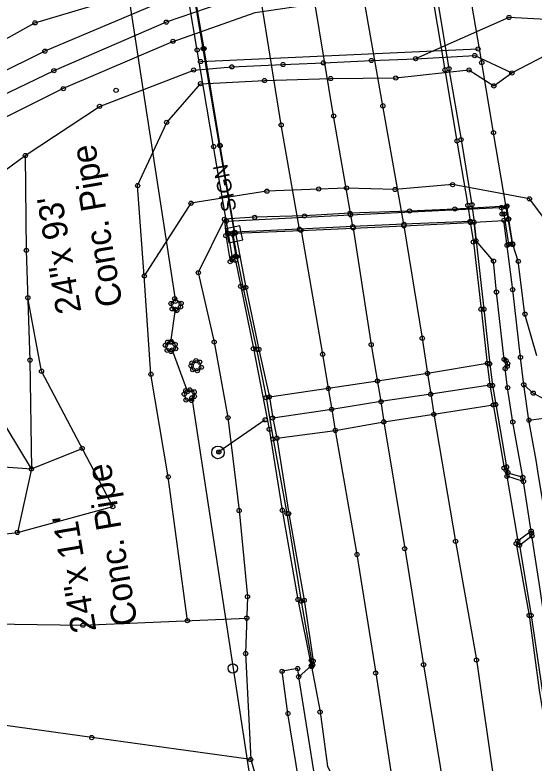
# Model space of a CAD drawing. Extents: x 21481721 to 21494985, y 8063982 to 8084842.
# Drawn here: x 21488039.9 to 21488164.1, y 8075079.6 to 8075258.6 of the extents above; entities that cross this region are included whole.
import ezdxf

# ---------------------------------------------------------------- set-up
doc = ezdxf.new("R2010")
doc.units = 0
for name, color, linetype in [('Bridge', 7, 'Continuous'), ('Default', 7, 'Continuous'), ('Drainage', 7, 'Continuous'), ('EXT_BL', 7, 'Continuous'), ('EXT_C', 7, 'Continuous'), ('EXT_CON', 7, 'Continuous'), ('EXT_CU', 7, 'Continuous'), ('EXT_D', 7, 'Continuous'), ('EXT_ENP', 7, 'Continuous'), ('EXT_EP', 7, 'Continuous'), ('EXT_GU', 7, 'Continuous'), ('EXT_SWK', 7, 'Continuous'), ('Roadways', 7, 'Continuous'), ('SurControl', 7, 'Continuous'), ('SurDrainage', 7, 'Continuous'), ('SurPointsNonDTM', 7, 'Continuous'), ('SurRoadPoints', 7, 'Continuous'), ('SurSurveyPoints', 7, 'Continuous'), ('Text', 7, 'Continuous')]:
    doc.layers.add(name, color=color, linetype=linetype)

msp = doc.modelspace()

# ---------------------------------------------------------------- linework, layer by layer
at = {"layer": 'Bridge'}
for points in [[(21488133.02, 8075208.53), (21488127.97, 8075236.87), (21488123.23, 8075263.68), (21488118.73, 8075292.88), (21488114.06, 8075318.67), (21488109.96, 8075344.62), (21488105.47, 8075369.72), (21488103.21, 8075384.48)], [(21488120.08, 8075385.72), (21488123.73, 8075364.06), (21488126.6, 8075347.14), (21488129.6, 8075329.59), (21488132.36, 8075313.39), (21488135.39, 8075295.32), (21488138.2, 8075278.59), (21488141.09, 8075261.71), (21488143.79, 8075245.75), (21488146.67, 8075228.8), (21488149.29, 8075213.2), (21488149.78, 8075209.03)], [(21488091.01, 8075206.3), (21488087.47, 8075227.14), (21488083.52, 8075250.23), (21488079.53, 8075273.88), (21488075.57, 8075297.2), (21488071.55, 8075321.1), (21488067.69, 8075343.72), (21488063.6, 8075368.19), (21488061.09, 8075383)], [(21488091.84, 8075206.37), (21488092.44, 8075206.59), (21488088.9, 8075227.4), (21488084.96, 8075250.55), (21488081, 8075274.15), (21488077.07, 8075297.44), (21488073.03, 8075321.28), (21488069.2, 8075343.93), (21488065.05, 8075368.47), (21488062.58, 8075383.09)], [(21488108, 8075207.36), (21488103.64, 8075232.31), (21488099.01, 8075261.23), (21488094.1, 8075289.47), (21488089.69, 8075316), (21488085.29, 8075341.96), (21488081.5, 8075365.43), (21488078.51, 8075383.22)], [(21488157.46, 8075212.67), (21488154.44, 8075230.46), (21488151.63, 8075247.25), (21488148.78, 8075264.05), (21488145.96, 8075280.82), (21488143.17, 8075297.55), (21488140.18, 8075315.22), (21488137.31, 8075331.99), (21488134.49, 8075348.81), (21488131.67, 8075365.48), (21488128.59, 8075383.27)], [(21488122.72, 8075363.95), (21488125.61, 8075347.18), (21488128.66, 8075329.41), (21488131.37, 8075313.38), (21488134.42, 8075295.1), (21488137.22, 8075278.46), (21488140.11, 8075261.55), (21488142.83, 8075245.48), (21488145.7, 8075228.45), (21488148.31, 8075213.06), (21488148.87, 8075209.24), (21488133.02, 8075208.53), (21488120.76, 8075207.97), (21488108, 8075207.36), (21488092.57, 8075206.62), (21488089.02, 8075227.38), (21488085.17, 8075250.55), (21488081.17, 8075274.1), (21488077.22, 8075297.45), (21488073.22, 8075321.29), (21488069.33, 8075343.94), (21488065.2, 8075368.55)]]:
    msp.add_lwpolyline(points, dxfattribs=at)
at = {"layer": 'Default'}
for p, q in [((21488150.73, 8075250.49), (21488150.73, 8075250.49)), ((21488084.33, 8075247.48), (21488084.33, 8075247.48))]:
    msp.add_line(p, q, dxfattribs=at)
for points in [[(21488120.76, 8075207.97), (21488116.18, 8075234.46), (21488111.59, 8075262.1), (21488106.7, 8075291.13), (21488102.31, 8075316.99), (21488098.02, 8075342.81), (21488093.73, 8075367.7), (21488091.12, 8075383.76)], [(21488084.33, 8075247.48), (21488150.73, 8075250.49)]]:
    msp.add_lwpolyline(points, dxfattribs=at)
at = {"layer": 'Drainage'}
for points in [[(21488064.32, 8075281.58), (21488078.34, 8075190.09)], [(21488077.22, 8075180.31), (21488078.31, 8075188.18)], [(21488077.53, 8075178.43), (21488081.18, 8075168.46)], [(21488082.26, 8075166.99), (21488119.44, 8074923.49)], [(21488099.78, 8075161.72), (21488088.7, 8075154.04)]]:
    msp.add_lwpolyline(points, dxfattribs=at)
at = {"layer": 'EXT_BL'}
for points in [[(21488255.94, 8075198.96), (21488256.72, 8075203.02), (21488252.15, 8075209.24), (21488240.15, 8075219.03), (21488220.61, 8075234.38), (21488204.16, 8075245.22), (21488188.67, 8075252.27), (21488174.57, 8075256.89), (21488165.62, 8075257.6), (21488158.14, 8075258.04), (21488135.81, 8075248.16)], [(21488081.2, 8075113.66), (21488076.62, 8075148.09), (21488072.47, 8075172.65), (21488070.88, 8075196.18), (21488069.27, 8075217.8), (21488076.23, 8075232.93), (21488084.31, 8075242.19), (21488099.64, 8075242.93), (21488115.47, 8075243.41), (21488131.06, 8075243.56), (21488148.57, 8075245.47), (21488154.52, 8075241.65), (21488158.85, 8075244.75), (21488168.94, 8075250.03), (21488180.68, 8075251.09), (21488194.28, 8075245.62), (21488207.18, 8075239.37), (21488220.09, 8075230.45), (21488233.03, 8075221.09), (21488244.21, 8075211.44), (21488255.94, 8075198.96)], [(21487989.15, 8075194.82), (21488024.32, 8075211.79), (21488042.4, 8075224.99), (21488060.17, 8075236.75), (21488082.7, 8075245.46), (21488091.82, 8075246.21), (21488104.06, 8075246.76), (21488113.72, 8075247.16), (21488125.22, 8075247.74), (21488135.81, 8075248.16), (21488149.96, 8075248.91), (21488158.85, 8075244.75)], [(21488042.4, 8075224.99), (21488042.63, 8075202.29), (21488043.51, 8075176.03), (21488043.85, 8075149.99), (21488040.5, 8075134.78)], [(21488174.3, 8075199.67), (21488163.05, 8075214.63), (21488144.64, 8075218.03), (21488130.89, 8075216.86), (21488119.28, 8075217.21), (21488112.61, 8075216.97), (21488100.21, 8075216.45), (21488082.04, 8075213.57), (21488070.88, 8075196.18)], [(21488164.8, 8075177.05), (21488161.97, 8075187.03), (21488160.37, 8075199.67), (21488159.04, 8075203.69), (21488157.7, 8075203.53), (21488159.04, 8075203.69), (21488158.08, 8075209.78), (21488157.64, 8075212.9), (21488145.19, 8075212.18), (21488134.35, 8075211.71), (21488120.1, 8075211.16), (21488109.21, 8075210.53), (21488097.3, 8075210.2), (21488090.05, 8075209.72), (21488090.38, 8075205.82), (21488091.42, 8075199.6), (21488092.69, 8075199.9), (21488093.95, 8075193.68), (21488096.97, 8075178.77), (21488100.77, 8075159.46), (21488103.9, 8075140.09), (21488107.64, 8075118.72), (21488110.83, 8075102.88)], [(21488043.85, 8075149.99), (21488034.94, 8075164.72), (21488026.75, 8075185.86), (21488024.32, 8075211.79)], [(21488090.05, 8075209.72), (21488083.79, 8075196.96), (21488087.59, 8075180.36), (21488090.9, 8075162.26), (21488093.56, 8075140.02), (21488095.56, 8075119.4), (21488095.13, 8075105.8), (21488096.33, 8075080.43), (21488104.12, 8075053.16), (21488107.13, 8075032.83), (21488107.57, 8075024.24)], [(21488108.38, 8075207.07), (21488113.55, 8075177.43), (21488114.9, 8075169.23), (21488115.72, 8075164.23), (21488116.59, 8075159.19), (21488121.77, 8075129.5), (21488126.26, 8075101.13), (21488130.75, 8075071.82), (21488134.72, 8075041.91), (21488137.54, 8075020.92)], [(21488132.99, 8075208.17), (21488137.39, 8075181.27), (21488138.65, 8075172.84), (21488139.41, 8075167.86), (21488140.16, 8075163.05), (21488145.37, 8075132.64), (21488150.36, 8075104.26), (21488154.62, 8075074.76), (21488158.43, 8075044.39), (21488160.97, 8075024.33)], [(21487978.49, 8075206.22), (21487989.15, 8075194.82), (21488003.15, 8075165.37), (21488025.25, 8075151.37), (21488043.85, 8075149.99), (21488056, 8075154.9)], [(21487946.5, 8075194.4), (21487955.26, 8075180.32), (21487972.57, 8075154.26), (21488000.89, 8075143.46), (21488026.66, 8075133.14), (21488040.5, 8075134.78), (21488063.33, 8075140.96)], [(21488063.33, 8075140.96), (21488046.29, 8075173.36), (21488043.01, 8075190.94)], [(21487912.64, 8075185.75), (21487921.08, 8075171.87), (21487949.76, 8075140.97), (21487968.9, 8075133.2), (21487985.64, 8075128.01), (21488002.28, 8075121.82), (21488028.81, 8075113.01), (21488056.18, 8075112.57), (21488095.4, 8075114.28)], [(21488096.33, 8075080.43), (21488058.31, 8075085.68), (21488028.39, 8075089.85), (21487994.89, 8075100.27), (21487957.6, 8075109.66), (21487932.27, 8075124.86), (21487903.55, 8075143.43), (21487883.81, 8075170.57), (21487884.18, 8075181.16)]]:
    msp.add_lwpolyline(points, dxfattribs=at)
for points in [[(21488078.15, 8075190.7), (21488077.25, 8075189.57), (21488077.55, 8075188.29), (21488078.64, 8075187.92), (21488079.54, 8075188.72), (21488079.69, 8075189.6)], [(21488077.28, 8075178.1), (21488078.39, 8075178.77), (21488078.24, 8075179.82), (21488077.36, 8075180.46), (21488076.47, 8075180.33), (21488075.9, 8075179.56), (21488076.35, 8075178.37)], [(21488084.51, 8075174.28), (21488084.13, 8075175.55), (21488083.25, 8075175.88), (21488082.3, 8075175.33), (21488082.07, 8075174.66), (21488082.47, 8075173.73), (21488083.55, 8075173.51)], [(21488080.42, 8075167.88), (21488080.85, 8075166.49), (21488082.17, 8075166.38), (21488082.85, 8075167.33), (21488082.82, 8075168.42), (21488081.77, 8075168.9), (21488080.8, 8075168.7)]]:
    msp.add_lwpolyline(points, close=True, dxfattribs=at)
at = {"layer": 'EXT_C'}
for points in [[(21488149.54, 8075267.07), (21488125.37, 8075267.11), (21488111.14, 8075266.15), (21488095.73, 8075263.72), (21488076.14, 8075256.92)], [(21488076.14, 8075256.92), (21488049.24, 8075245.29), (21488025.33, 8075233.8), (21488002.44, 8075221.66), (21487975.58, 8075210.32)], [(21488120.86, 8075207.63), (21488125.18, 8075179.72), (21488127.51, 8075166.09), (21488128.19, 8075161.24), (21488133.19, 8075130.91), (21488137.71, 8075103.12), (21488142.46, 8075073.86), (21488146.04, 8075043.29), (21488148.72, 8075022.35)], [(21488162.92, 8075161.65), (21488168.9, 8075162.46), (21488174.55, 8075163.41), (21488191.26, 8075166.05), (21488206.71, 8075168.67), (21488225.5, 8075172.64), (21488240.24, 8075175.89), (21488255.09, 8075179.82), (21488259.45, 8075182.69), (21488264.06, 8075187.24), (21488265.22, 8075188.35), (21488270.84, 8075196.54), (21488271.9, 8075198.18), (21488274.4, 8075201.93)]]:
    msp.add_lwpolyline(points, dxfattribs=at)
at = {"layer": 'EXT_CON'}
for points in [[(21488091.01, 8075206.3), (21488091.01, 8075206.32), (21488090.5, 8075209.29), (21488120.24, 8075210.81), (21488157.47, 8075212.67)], [(21488157.47, 8075212.67), (21488157.97, 8075209.72), (21488157.97, 8075209.72)], [(21488152.95, 8075175.24), (21488138.65, 8075172.84), (21488126.67, 8075171.02), (21488114.9, 8075169.23), (21488100.81, 8075167.18)], [(21488102.6, 8075157.33), (21488116.59, 8075159.19), (21488128.19, 8075161.24), (21488140.16, 8075163.05), (21488154.36, 8075165.29)], [(21488157.66, 8075148.21), (21488157.89, 8075149.08), (21488161.45, 8075147.98)], [(21488161.6, 8075146.99), (21488157.66, 8075148.21)], [(21488163.46, 8075135.1), (21488160.23, 8075132.7)], [(21488160.68, 8075131.74), (21488163.64, 8075133.94)]]:
    msp.add_lwpolyline(points, dxfattribs=at)
for points in [[(21488157.46, 8075212.67), (21488156.34, 8075212.53), (21488156.51, 8075211), (21488156.94, 8075211.01), (21488158.07, 8075203.74), (21488158.98, 8075203.87)], [(21488091.01, 8075206.3), (21488091.84, 8075206.37), (21488092.76, 8075200.94), (21488092.3, 8075200.55), (21488091.97, 8075200.5)]]:
    msp.add_lwpolyline(points, close=True, dxfattribs=at)
at = {"layer": 'EXT_CU'}
for points in [[(21488148.88, 8075208.96), (21488149.78, 8075209.03), (21488150.26, 8075204.57), (21488152.14, 8075188.2), (21488153.54, 8075175.14), (21488154.22, 8075169.95), (21488154.97, 8075165.39), (21488157.56, 8075150.47), (21488157.89, 8075149.08)], [(21488092.68, 8075206.42), (21488092.06, 8075206.09), (21488093.02, 8075200.8), (21488094.51, 8075193.26), (21488097.74, 8075178.62), (21488100.03, 8075167.04), (21488101.69, 8075157.13), (21488105.02, 8075139.32), (21488108.45, 8075118.33), (21488110.85, 8075104.14), (21488110.83, 8075102.88)], [(21488160.23, 8075132.7), (21488160.68, 8075131.74), (21488163.44, 8075114.9), (21488166.11, 8075097.01), (21488168.7, 8075078.69), (21488169.82, 8075071.25)]]:
    msp.add_lwpolyline(points, dxfattribs=at)
at = {"layer": 'EXT_D'}
msp.add_lwpolyline([(21487971.05, 8075220.59), (21488002, 8075235.48), (21488023.55, 8075245), (21488044.71, 8075256.74), (21488066.12, 8075263.19), (21488069.65, 8075264.54)], dxfattribs=at)
at = {"layer": 'EXT_ENP'}
msp.add_lwpolyline([(21488110.83, 8075102.88), (21488107.83, 8075100.24)], dxfattribs=at)
at = {"layer": 'EXT_EP'}
for points in [[(21488074.68, 8075261.58), (21488095.95, 8075269.14), (21488109.99, 8075271.51), (21488127.42, 8075272.46), (21488140.89, 8075272.69), (21488148.98, 8075272.17), (21488140.89, 8075272.69), (21488127.42, 8075272.46), (21488109.99, 8075271.51), (21488095.95, 8075269.14), (21488074.68, 8075261.58), (21488047.08, 8075249.97), (21488022.91, 8075238.02), (21488000.35, 8075226.23), (21487973.56, 8075214.92)], [(21488077.75, 8075252.32), (21488097.4, 8075259.23), (21488112.61, 8075261.44), (21488127.06, 8075262.22), (21488150.11, 8075262.04)], [(21488077.75, 8075252.32), (21488051.49, 8075241), (21488027.78, 8075229.25), (21488004.69, 8075217.52), (21487978.49, 8075206.22)], [(21488092.68, 8075206.42), (21488108.38, 8075207.07), (21488120.86, 8075207.63), (21488132.99, 8075208.17), (21488148.88, 8075208.96)], [(21488166.58, 8075166.69), (21488163.95, 8075168.13), (21488161.68, 8075170.12)]]:
    msp.add_lwpolyline(points, dxfattribs=at)
at = {"layer": 'EXT_GU'}
for points in [[(21488148.88, 8075208.96), (21488149.63, 8075204.28), (21488151.46, 8075188.21), (21488152.95, 8075175.24), (21488153.55, 8075169.99)], [(21488092.68, 8075206.42), (21488095.15, 8075193.4), (21488098.3, 8075178.58), (21488100.81, 8075167.18)], [(21488153.55, 8075169.99), (21488156.97, 8075150.19), (21488157.42, 8075149.69), (21488160.23, 8075132.7), (21488159.87, 8075132.09), (21488162.98, 8075114.92), (21488165.38, 8075097.01), (21488168.39, 8075078.75), (21488169.3, 8075071.21), (21488169.96, 8075070.45), (21488171.12, 8075060.48), (21488172.17, 8075054.01), (21488171.86, 8075053.64), (21488173.78, 8075038.75), (21488175.06, 8075026.65)], [(21488100.81, 8075167.18), (21488101.61, 8075162.16), (21488102.6, 8075157.33)], [(21488102.6, 8075157.33), (21488105.44, 8075139.29), (21488109.15, 8075118.54), (21488111.29, 8075104.02), (21488111.18, 8075103.02), (21488110.92, 8075102.68), (21488112.94, 8075091.81), (21488114.73, 8075078.75), (21488115.3, 8075077.75), (21488117.77, 8075061.5), (21488119.37, 8075050.61), (21488120.56, 8075040.74), (21488122.18, 8075028.45), (21488122.27, 8075027.73), (21488121.7, 8075027.74)]]:
    msp.add_lwpolyline(points, dxfattribs=at)
at = {"layer": 'EXT_SWK'}
for points in [[(21488178.98, 8075027.15), (21488176.91, 8075044.19), (21488175.56, 8075054.84), (21488173.45, 8075070.02), (21488171, 8075085.56), (21488168.15, 8075103.64), (21488165.59, 8075121.19), (21488163.54, 8075134.55), (21488161.45, 8075147.98), (21488159.06, 8075161.21), (21488157.82, 8075169.42), (21488157.25, 8075174), (21488157.72, 8075174.53), (21488157.82, 8075175.18), (21488157.45, 8075175.87), (21488156.99, 8075176.18), (21488155.14, 8075192.3), (21488154.44, 8075199.72), (21488150.26, 8075204.57), (21488149.78, 8075209.03), (21488156.95, 8075209.47)], [(21488182.86, 8075027.74), (21488180.81, 8075044.85), (21488179.45, 8075055.18), (21488177.29, 8075070.71), (21488174.88, 8075086.16), (21488172.05, 8075104.01), (21488169.42, 8075121.77), (21488167.44, 8075135.15), (21488165.21, 8075148.41), (21488164.65, 8075152.1), (21488162.92, 8075161.65), (21488161.68, 8075170.12), (21488160.89, 8075176.68), (21488159.03, 8075192.88), (21488156.95, 8075209.47)], [(21488118.7, 8075024.94), (21488116.46, 8075039.34), (21488115.21, 8075051.13), (21488111.46, 8075077.76), (21488107.83, 8075100.24), (21488107.59, 8075102.21), (21488103.86, 8075101.54)], [(21488114.49, 8075024.43), (21488112.99, 8075039.36), (21488111.65, 8075049.81), (21488107.88, 8075075.32), (21488105.26, 8075091.45), (21488103.86, 8075101.54)]]:
    msp.add_lwpolyline(points, dxfattribs=at)
at = {"layer": 'Roadways'}
msp.add_lwpolyline([(21488153.55, 8075169.99), (21488139.41, 8075167.86), (21488127.51, 8075166.09), (21488115.72, 8075164.23), (21488101.61, 8075162.16)], dxfattribs=at)
at = {"layer": 'SurControl'}
msp.add_circle((21488092.04, 8075102.22), 1.12, dxfattribs=at)
at = {"layer": 'SurDrainage'}
for radius in [1.5, 0.25]:
    msp.add_circle((21488088.51, 8075153.93), radius, dxfattribs=at)
at = {"layer": 'SurPointsNonDTM'}
for centre in [(21488083.52, 8075250.23), (21488084.96, 8075250.55), (21488085.17, 8075250.55), (21488150.73, 8075250.49), (21488084.33, 8075247.48), (21488151.63, 8075247.25), (21488142.83, 8075245.48), (21488143.79, 8075245.75), (21488064.12, 8075240.58), (21488064.12, 8075240.58), (21488127.97, 8075236.87), (21488116.18, 8075234.46), (21488103.64, 8075232.31), (21488154.44, 8075230.46), (21488145.7, 8075228.45), (21488146.67, 8075228.8), (21488087.47, 8075227.14), (21488088.9, 8075227.4), (21488089.02, 8075227.38), (21488148.31, 8075213.06), (21488149.29, 8075213.2), (21488157.46, 8075212.67), (21488133.02, 8075208.53), (21488133.02, 8075208.53), (21488148.87, 8075209.24), (21488149.78, 8075209.03), (21488092.44, 8075206.59), (21488092.57, 8075206.62), (21488108, 8075207.36), (21488108, 8075207.36), (21488120.76, 8075207.97), (21488120.76, 8075207.97), (21488091.01, 8075206.3), (21488091.84, 8075206.37), (21488078.34, 8075190.09), (21488078.31, 8075188.18), (21488077.22, 8075180.31), (21488077.53, 8075178.43), (21488153.55, 8075169.99), (21488081.18, 8075168.46), (21488139.41, 8075167.86), (21488082.26, 8075166.99), (21488127.51, 8075166.09), (21488115.72, 8075164.23), (21488101.61, 8075162.16), (21488099.78, 8075161.72), (21488088.7, 8075154.04)]:
    msp.add_circle(centre, 0.5, dxfattribs=at)
at = {"layer": 'SurRoadPoints'}
msp.add_lwpolyline([(21488094.09, 8075206.47), (21488094.09, 8075206.47), (21488093.74, 8075208.14), (21488090.39, 8075207.45), (21488091.08, 8075204.09), (21488094.43, 8075204.79), (21488094.09, 8075206.46)], dxfattribs=at)
at = {"layer": 'SurSurveyPoints'}
for centre in [(21488044.71, 8075256.74), (21488076.14, 8075256.92), (21488076.14, 8075256.92), (21488158.14, 8075258.04), (21488077.75, 8075252.32), (21488077.75, 8075252.32), (21488047.08, 8075249.97), (21488125.22, 8075247.74), (21488135.81, 8075248.16), (21488135.81, 8075248.16), (21488149.96, 8075248.91), (21488091.82, 8075246.21), (21488104.06, 8075246.76), (21488113.72, 8075247.16), (21488049.24, 8075245.29), (21488082.7, 8075245.46), (21488082.7, 8075245.46), (21488148.57, 8075245.47), (21488158.85, 8075244.75), (21488158.85, 8075244.75), (21488099.64, 8075242.93), (21488115.47, 8075243.41), (21488131.06, 8075243.56), (21488051.49, 8075241), (21488084.31, 8075242.19), (21488084.31, 8075242.19), (21488154.52, 8075241.65), (21488154.52, 8075241.65), (21488060.17, 8075236.75), (21488076.23, 8075232.93), (21488042.4, 8075224.99), (21488042.4, 8075224.99), (21488069.27, 8075217.8), (21488144.64, 8075218.03), (21488100.21, 8075216.45), (21488112.61, 8075216.97), (21488119.28, 8075217.21), (21488130.89, 8075216.86), (21488163.05, 8075214.63), (21488082.04, 8075213.57), (21488145.19, 8075212.18), (21488156.34, 8075212.53), (21488157.47, 8075212.67), (21488157.46, 8075212.67), (21488157.46, 8075212.67), (21488157.47, 8075212.67), (21488157.64, 8075212.9), (21488157.64, 8075212.9), (21488097.3, 8075210.2), (21488109.21, 8075210.53), (21488120.1, 8075211.16), (21488120.24, 8075210.81), (21488134.35, 8075211.71), (21488156.51, 8075211), (21488156.94, 8075211.01), (21488090.05, 8075209.72), (21488090.05, 8075209.72), (21488090.05, 8075209.72), (21488090.5, 8075209.29), (21488148.88, 8075208.96), (21488148.88, 8075208.96), (21488148.88, 8075208.96), (21488149.78, 8075209.03), (21488149.78, 8075209.03), (21488156.95, 8075209.47), (21488156.95, 8075209.47), (21488157.97, 8075209.72), (21488157.97, 8075209.72), (21488158.08, 8075209.78), (21488108.38, 8075207.07), (21488108.38, 8075207.07), (21488120.86, 8075207.63), (21488120.86, 8075207.63), (21488132.99, 8075208.17), (21488132.99, 8075208.17), (21488090.38, 8075205.82), (21488091.01, 8075206.32), (21488091.01, 8075206.3), (21488091.01, 8075206.3), (21488091.01, 8075206.3), (21488091.84, 8075206.37), (21488092.06, 8075206.09), (21488092.68, 8075206.42), (21488092.68, 8075206.42), (21488092.68, 8075206.42), (21488149.63, 8075204.28), (21488150.26, 8075204.57), (21488150.26, 8075204.57), (21488157.7, 8075203.53), (21488158.07, 8075203.74), (21488158.98, 8075203.87), (21488159.04, 8075203.69), (21488159.04, 8075203.69), (21488042.63, 8075202.29), (21488091.42, 8075199.6), (21488091.97, 8075200.5), (21488092.3, 8075200.55), (21488092.69, 8075199.9), (21488092.76, 8075200.94), (21488093.02, 8075200.8), (21488154.44, 8075199.72), (21488160.37, 8075199.67), (21488070.88, 8075196.18), (21488083.79, 8075196.96), (21488093.95, 8075193.68), (21488094.51, 8075193.26), (21488095.15, 8075193.4), (21488155.14, 8075192.3), (21488159.03, 8075192.88), (21488043.01, 8075190.94), (21488078.15, 8075190.7), (21488078.15, 8075190.7), (21488077.25, 8075189.57), (21488079.54, 8075188.72), (21488079.69, 8075189.6), (21488077.55, 8075188.29), (21488078.64, 8075187.92), (21488151.46, 8075188.21), (21488152.14, 8075188.2), (21488161.97, 8075187.03), (21488076.47, 8075180.33), (21488077.36, 8075180.46), (21488078.24, 8075179.82), (21488087.59, 8075180.36), (21488125.18, 8075179.72), (21488137.39, 8075181.27), (21488075.9, 8075179.56), (21488076.35, 8075178.37), (21488077.28, 8075178.1), (21488077.28, 8075178.1), (21488078.39, 8075178.77), (21488096.97, 8075178.77), (21488097.74, 8075178.62), (21488098.3, 8075178.58), (21488113.55, 8075177.43), (21488156.99, 8075176.18), (21488160.89, 8075176.68), (21488043.51, 8075176.03), (21488082.07, 8075174.66), (21488082.3, 8075175.33), (21488083.25, 8075175.88), (21488084.13, 8075175.55), (21488152.95, 8075175.24), (21488152.95, 8075175.24), (21488153.54, 8075175.14), (21488157.45, 8075175.87), (21488157.72, 8075174.53), (21488157.82, 8075175.18), (21488046.29, 8075173.36), (21488072.47, 8075172.65), (21488082.47, 8075173.73), (21488083.55, 8075173.51), (21488084.51, 8075174.28), (21488084.51, 8075174.28), (21488138.65, 8075172.84), (21488138.65, 8075172.84), (21488157.25, 8075174), (21488126.67, 8075171.02), (21488114.9, 8075169.23), (21488114.9, 8075169.23), (21488153.55, 8075169.99), (21488153.55, 8075169.99), (21488154.22, 8075169.95), (21488157.82, 8075169.42), (21488161.68, 8075170.12), (21488161.68, 8075170.12), (21488080.42, 8075167.88), (21488080.42, 8075167.88), (21488080.8, 8075168.7), (21488081.77, 8075168.9), (21488082.82, 8075168.42), (21488082.85, 8075167.33), (21488100.81, 8075167.18), (21488100.81, 8075167.18), (21488100.81, 8075167.18), (21488139.41, 8075167.86), (21488163.95, 8075168.13), (21488080.85, 8075166.49), (21488082.17, 8075166.38), (21488100.03, 8075167.04), (21488127.51, 8075166.09), (21488154.97, 8075165.39), (21488115.72, 8075164.23), (21488154.36, 8075165.29), (21488090.9, 8075162.26), (21488101.61, 8075162.16), (21488140.16, 8075163.05), (21488140.16, 8075163.05), (21488128.19, 8075161.24), (21488128.19, 8075161.24), (21488159.06, 8075161.21), (21488162.92, 8075161.65), (21488162.92, 8075161.65), (21488100.77, 8075159.46), (21488116.59, 8075159.19), (21488116.59, 8075159.19), (21488101.69, 8075157.13), (21488102.6, 8075157.33), (21488102.6, 8075157.33), (21488102.6, 8075157.33), (21488056, 8075154.9), (21488043.85, 8075149.99), (21488043.85, 8075149.99), (21488043.85, 8075149.99), (21488156.97, 8075150.19), (21488157.42, 8075149.69), (21488157.56, 8075150.47), (21488076.62, 8075148.09), (21488157.66, 8075148.21), (21488157.66, 8075148.21), (21488157.89, 8075149.08), (21488157.89, 8075149.08), (21488161.45, 8075147.98), (21488161.45, 8075147.98), (21488161.6, 8075146.99), (21488063.33, 8075140.96), (21488063.33, 8075140.96), (21488093.56, 8075140.02), (21488103.9, 8075140.09), (21488105.02, 8075139.32), (21488105.44, 8075139.29), (21488163.46, 8075135.1), (21488040.5, 8075134.78), (21488040.5, 8075134.78), (21488163.54, 8075134.55), (21488163.64, 8075133.94), (21488145.37, 8075132.64), (21488159.87, 8075132.09), (21488160.23, 8075132.7), (21488160.23, 8075132.7), (21488160.23, 8075132.7), (21488160.68, 8075131.74), (21488160.68, 8075131.74), (21488133.19, 8075130.91), (21488121.77, 8075129.5), (21488095.56, 8075119.4), (21488107.64, 8075118.72), (21488108.45, 8075118.33), (21488109.15, 8075118.54), (21488081.2, 8075113.66), (21488095.4, 8075114.28), (21488162.98, 8075114.92), (21488163.44, 8075114.9), (21488056.18, 8075112.57), (21488095.13, 8075105.8), (21488110.83, 8075102.88), (21488110.83, 8075102.88), (21488110.83, 8075102.88), (21488110.85, 8075104.14), (21488110.92, 8075102.68), (21488111.18, 8075103.02), (21488111.29, 8075104.02), (21488137.71, 8075103.12), (21488150.36, 8075104.26), (21488103.86, 8075101.54), (21488103.86, 8075101.54), (21488107.59, 8075102.21), (21488126.26, 8075101.13), (21488107.83, 8075100.24), (21488107.83, 8075100.24), (21488105.26, 8075091.45), (21488112.94, 8075091.81), (21488058.31, 8075085.68), (21488096.33, 8075080.43), (21488096.33, 8075080.43)]:
    msp.add_circle(centre, 0.5, dxfattribs=at)

# ---------------------------------------------------------------- texts
at = {"layer": 'SurRoadPoints'}
msp.add_text('SIGN', height=3.498, rotation=101.6929, dxfattribs=at).set_placement((21488092.99, 8075211.96))
at = {"layer": 'Text'}
for s, rotation, p in [('Conc. Pipe', 99.6962, (21488065.7, 8075189.31)), ('24"x 93\'', 99.6962, (21488055.84, 8075187.63)), ('Conc. Pipe', 99.5377, (21488069.28, 8075112.94)), ('24"x 11\'', 99.5377, (21488059.42, 8075111.28))]:
    msp.add_text(s, height=6, rotation=rotation, dxfattribs=at).set_placement(p)

doc.saveas('drawing.dxf')
